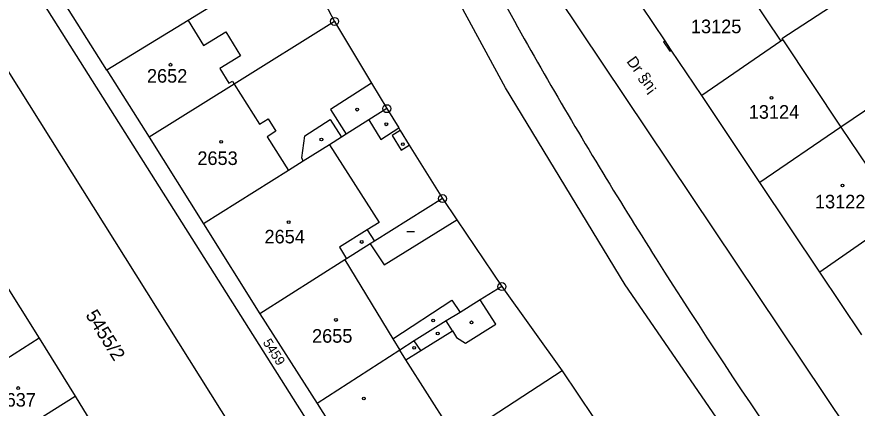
# Model space of a CAD drawing. Extents: x -822293 to -820259, y -1071573 to -1068794.
# Drawn here: x -820673 to -820567.6, y -1071273.6 to -1071224.6 of the extents above; entities that cross this region are included whole.
import ezdxf

# ---------------------------------------------------------------- set-up
doc = ezdxf.new("R2010")
doc.units = 0
for name, color, linetype in [('Vrstva 1', 7, 'Continuous'), ('Vrstva 10', 7, 'Continuous'), ('Vrstva 15', 7, 'Continuous'), ('Vrstva 18', 7, 'Continuous'), ('Vrstva 19', 7, 'Continuous'), ('Vrstva 2', 7, 'Continuous'), ('Vrstva 24', 7, 'Continuous'), ('Vrstva 25', 7, 'Continuous'), ('Vrstva 3', 7, 'Continuous'), ('Vrstva 4', 7, 'Continuous')]:
    doc.layers.add(name, color=color, linetype=linetype)

msp = doc.modelspace()

# ---------------------------------------------------------------- linework, layer by layer
at = {"layer": 'Vrstva 1'}
for p, q in [((-820613.1, -1071210.27), (-820567.96, -1071277.63)), ((-820636.66, -1071218.6), (-820633.16, -1071225.15)), ((-820565.25, -1071219.52), (-820577.08, -1071227.33)), ((-820671.47, -1071220.04), (-820614.75, -1071309.77)), ((-820622.76, -1071313.08), (-820677.95, -1071225.19)), ((-820633.16, -1071225.15), (-820645.74, -1071233.01)), ((-820633.16, -1071225.15), (-820628.53, -1071232.88)), ((-820577.08, -1071227.33), (-820576.97, -1071227.46)), ((-820562.23, -1071233.35), (-820569.68, -1071238.4)), ((-820625.11, -1071238.51), (-820624.92, -1071238.81)), ((-820631.69, -1071239.28), (-820632.28, -1071239.66)), ((-820623.79, -1071240.65), (-820619.63, -1071247.37)), ((-820617.84, -1071250.03), (-820612.18, -1071258.39)), ((-820612.18, -1071258.39), (-820614.9, -1071260.07)), ((-820612.18, -1071258.39), (-820604.65, -1071268.97)), ((-820604.65, -1071268.97), (-820617.86, -1071277.55)), ((-820604.65, -1071268.97), (-820600.69, -1071274.81))]:
    msp.add_line(p, q, dxfattribs=at)
at = {"layer": 'Vrstva 10'}
for p, q in [((-820611.74, -1071233.47), (-820624.12, -1071210.63)), ((-820596.75, -1071258.19), (-820611.74, -1071233.47)), ((-820561.35, -1071309.57), (-820596.75, -1071258.19))]:
    msp.add_line(p, q, dxfattribs=at)
msp.add_spline([(-820648.37, -1071145.75), (-820635.21, -1071175.92), (-820619.77, -1071208), (-820606.88, -1071231.72), (-820592.84, -1071254.92), (-820557.31, -1071306.48), (-820522.72, -1071349.67), (-820487.72, -1071388.36), (-820440.04, -1071434.15), (-820382.01, -1071481.32), (-820258.78, -1071573.12)], degree=3, dxfattribs=at)
at = {"layer": 'Vrstva 2'}
for p, q in [((-820661.69, -1071231.28), (-820669.63, -1071218.58)), ((-820648.17, -1071222.99), (-820651.49, -1071225.03)), ((-820591.73, -1071227.59), (-820594.66, -1071223.23)), ((-820651.49, -1071225.03), (-820661.69, -1071231.28)), ((-820590.95, -1071228.74), (-820591.73, -1071227.59)), ((-820577.21, -1071227.63), (-820587.11, -1071234.42)), ((-820576.97, -1071227.46), (-820577.21, -1071227.63)), ((-820587.11, -1071234.42), (-820590.95, -1071228.74)), ((-820661.69, -1071231.28), (-820656.41, -1071239.65)), ((-820645.74, -1071233.01), (-820656.41, -1071239.65)), ((-820628.53, -1071232.88), (-820626.61, -1071236.09)), ((-820579.87, -1071245.35), (-820587.11, -1071234.42)), ((-820626.61, -1071236.09), (-820628.85, -1071237.5)), ((-820626.61, -1071236.09), (-820625.11, -1071238.51)), ((-820628.85, -1071237.5), (-820631.69, -1071239.28)), ((-820569.68, -1071238.4), (-820579.87, -1071245.35)), ((-820656.41, -1071239.65), (-820649.59, -1071250.53)), ((-820632.28, -1071239.66), (-820633.8, -1071240.61)), ((-820624.92, -1071238.81), (-820623.79, -1071240.65)), ((-820633.8, -1071240.61), (-820637.11, -1071242.69)), ((-820637.11, -1071242.69), (-820638.94, -1071243.84)), ((-820638.94, -1071243.84), (-820649.59, -1071250.53)), ((-820572.35, -1071256.57), (-820579.87, -1071245.35)), ((-820619.63, -1071247.37), (-820628.17, -1071252.72)), ((-820619.63, -1071247.37), (-820617.84, -1071250.03)), ((-820562.23, -1071249.55), (-820572.35, -1071256.57)), ((-820649.59, -1071250.53), (-820642.52, -1071261.82)), ((-820628.68, -1071253.04), (-820631.65, -1071254.9)), ((-820628.17, -1071252.72), (-820628.68, -1071253.04)), ((-820631.89, -1071255.05), (-820642.52, -1071261.82)), ((-820631.65, -1071254.9), (-820631.89, -1071255.05)), ((-820567.06, -1071264.43), (-820572.35, -1071256.57)), ((-820674.96, -1071257.25), (-820670.17, -1071264.87)), ((-820614.9, -1071260.07), (-820617.43, -1071261.64)), ((-820642.52, -1071261.82), (-820635.34, -1071273.05)), ((-820617.43, -1071261.64), (-820619.15, -1071262.7)), ((-820619.15, -1071262.7), (-820623.18, -1071265.19)), ((-820670.17, -1071264.87), (-820679.93, -1071271.06)), ((-820670.17, -1071264.87), (-820665.69, -1071272.14)), ((-820623.18, -1071265.19), (-820624.98, -1071266.36)), ((-820624.98, -1071266.36), (-820635.34, -1071273.05)), ((-820675.71, -1071278.4), (-820665.69, -1071272.14)), ((-820665.69, -1071272.14), (-820657.82, -1071284.93)), ((-820635.34, -1071273.05), (-820628.38, -1071284.03))]:
    msp.add_line(p, q, dxfattribs=at)
at = {"layer": 'Vrstva 24'}
for centre, radius in [((-820633.16, -1071225.15), 0.5), ((-820633.16, -1071225.15), 0.0327), ((-820626.61, -1071236.09), 0.5), ((-820626.61, -1071236.09), 0.0327), ((-820619.63, -1071247.37), 0.5), ((-820619.63, -1071247.37), 0.0327), ((-820612.18, -1071258.39), 0.5), ((-820612.18, -1071258.39), 0.0327)]:
    msp.add_circle(centre, radius, dxfattribs=at)
at = {"layer": 'Vrstva 25'}
msp.add_line((-820624.12, -1071251.47), (-820623.12, -1071251.47), dxfattribs=at)
for centre in [(-820653.72, -1071230.58), (-820578.4, -1071234.73), (-820630.33, -1071236.21), (-820626.67, -1071238.05), (-820634.81, -1071239.95), (-820647.38, -1071240.24), (-820624.61, -1071240.54), (-820569.5, -1071245.72), (-820638.91, -1071250.33), (-820629.76, -1071252.8), (-820632.98, -1071262.58), (-820620.81, -1071262.65), (-820616, -1071262.88), (-820620.23, -1071264.28), (-820623.17, -1071266.08), (-820672.81, -1071271.11), (-820629.49, -1071272.41)]:
    msp.add_circle(centre, 0.175, dxfattribs=at)
at = {"layer": 'Vrstva 3'}
for p, q in [((-820581.88, -1071220.64), (-820577.21, -1071227.63)), ((-820651.49, -1071225.03), (-820649.57, -1071228.16)), ((-820649.57, -1071228.16), (-820646.79, -1071226.44)), ((-820646.79, -1071226.44), (-820644.93, -1071229.47)), ((-820576.97, -1071227.46), (-820569.68, -1071238.4)), ((-820644.93, -1071229.47), (-820647.55, -1071231.07)), ((-820647.55, -1071231.07), (-820646.42, -1071232.91)), ((-820646.42, -1071232.91), (-820645.97, -1071232.64)), ((-820645.97, -1071232.64), (-820645.74, -1071233.01)), ((-820645.74, -1071233.01), (-820642.58, -1071238.05)), ((-820628.53, -1071232.88), (-820633.67, -1071236.2)), ((-820633.67, -1071236.2), (-820631.69, -1071239.28)), ((-820642.58, -1071238.05), (-820641.49, -1071237.36)), ((-820641.49, -1071237.36), (-820640.51, -1071238.92)), ((-820636.88, -1071239.48), (-820633.69, -1071237.44)), ((-820633.69, -1071237.44), (-820632.28, -1071239.66)), ((-820628.85, -1071237.5), (-820627.37, -1071239.95)), ((-820627.37, -1071239.95), (-820625.11, -1071238.51)), ((-820569.68, -1071238.4), (-820562.23, -1071249.55)), ((-820640.51, -1071238.92), (-820641.6, -1071239.61)), ((-820641.6, -1071239.61), (-820638.94, -1071243.84)), ((-820637.27, -1071242.25), (-820636.88, -1071239.48)), ((-820624.92, -1071238.81), (-820625.94, -1071239.44)), ((-820625.94, -1071239.44), (-820624.81, -1071241.28)), ((-820633.8, -1071240.61), (-820627.56, -1071250.34)), ((-820624.81, -1071241.28), (-820623.79, -1071240.65)), ((-820637.11, -1071242.69), (-820637.27, -1071242.25)), ((-820627.56, -1071250.34), (-820629.08, -1071251.28)), ((-820626.95, -1071255.67), (-820617.84, -1071250.03)), ((-820629.08, -1071251.28), (-820632.56, -1071253.45)), ((-820629.08, -1071251.28), (-820628.17, -1071252.72)), ((-820632.56, -1071253.45), (-820631.65, -1071254.9)), ((-820628.68, -1071253.04), (-820626.95, -1071255.67)), ((-820631.89, -1071255.05), (-820625.85, -1071264.94)), ((-820625.85, -1071264.94), (-820618.44, -1071260.1)), ((-820618.44, -1071260.1), (-820617.43, -1071261.64)), ((-820612.93, -1071263.11), (-820614.9, -1071260.07)), ((-820618.38, -1071263.94), (-820619.15, -1071262.7)), ((-820622.34, -1071266.39), (-820618.38, -1071263.94)), ((-820618.38, -1071263.94), (-820617.87, -1071264.76)), ((-820616.75, -1071265.5), (-820612.93, -1071263.11)), ((-820625.85, -1071264.94), (-820624.98, -1071266.36)), ((-820617.87, -1071264.76), (-820616.75, -1071265.5)), ((-820622.34, -1071266.39), (-820623.18, -1071265.19)), ((-820624.21, -1071267.57), (-820624.98, -1071266.36)), ((-820624.21, -1071267.57), (-820622.34, -1071266.39)), ((-820617.86, -1071277.55), (-820624.21, -1071267.57))]:
    msp.add_line(p, q, dxfattribs=at)
at = {"layer": 'Vrstva 4'}
for p, q in [((-820591.73, -1071227.59), (-820591.92, -1071227.71)), ((-820591.92, -1071227.71), (-820591.14, -1071228.87)), ((-820591.14, -1071228.87), (-820590.95, -1071228.74))]:
    msp.add_line(p, q, dxfattribs=at)

# ---------------------------------------------------------------- texts
at = {"layer": 'Vrstva 15'}
msp.add_text('Dr\xa0§n¡', height=1.4, rotation=306.33957, dxfattribs=at).set_placement((-820596.62, -1071230.175))
at = {"layer": 'Vrstva 18'}
for s, height, rotation, p in [('5455/2', 1.7, 301.88979, (-820664.425, -1071261.956)), ('5459', 1.2, 302.59323, (-820642.198, -1071265.404))]:
    msp.add_text(s, height=height, rotation=rotation, dxfattribs=at).set_placement(p)
at = {"layer": 'Vrstva 19'}
for s, p in [('13125', (-820588.49, -1071226.63)), ('2652', (-820656.674, -1071232.83)), ('13124', (-820581.238, -1071237.35)), ('2653', (-820650.356, -1071243.15)), ('13122', (-820572.944, -1071248.59)), ('2654', (-820641.939, -1071252.98)), ('2655', (-820635.98, -1071265.43)), ('2637', (-820675.649, -1071273.44))]:
    msp.add_text(s, height=1.7, dxfattribs=at).set_placement(p)

doc.saveas('drawing.dxf')
